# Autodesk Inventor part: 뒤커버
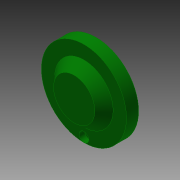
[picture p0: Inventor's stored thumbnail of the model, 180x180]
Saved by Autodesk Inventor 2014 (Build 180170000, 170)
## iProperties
Created: 2017-08
Part Number: 뒤커버
Material: 알루미늄 6061
Document SubType Name: Modeling
Designer: mduedu
Density: 1 g/cm^3
Appearance: 진녹색
Author: mduedu
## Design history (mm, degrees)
sketch "스케치1"
  geometry: C1 r 35 at (0, 0); 1 further point
  constraints: 1 centre point, 1 coincident
  dimensions: "d0" = 70 diameter of C1
extrude "돌출1" new body sketch "스케치1" distance "d1" = 10; taper "d2" = 0 deg
sketch "스케치2"
  geometry: C1 r 24 at (0, 0); 1 further point
  constraints: 1 centre point, 1 coincident
  dimensions: "d3" = 48 diameter of C1
node "작업 평면1"
sketch "스케치3"
  geometry: C1 r 17 at (0, 0); 1 further point
  constraints: 1 centre point, 1 coincident
  dimensions: "d5" = 34 diameter of C1
feature "로프트1" sketch "스케치3" dims "d6" = 0, "d7" = 90 deg, "d8" = 0, "d9" = 90 deg
sketch "스케치4"
  geometry: C1 r 24 at (0, 0) reference; 1 further point
extrude "돌출2" join sketch "스케치4" distance "d10" = 8; taper "d11" = 0 deg
hole "구멍1" diameter "d14" = 40; stored, may be unused: countersink angle "d18" = 90 deg, drill point angle "d20" = 0 deg; dims "d12" = 10, "d13" = 10, "d15" = 6, "d16" = 4, "d17" = 2, "d19" = 12
hole "구멍2" diameter "d23" = 34; stored, may be unused: countersink angle "d27" = 90 deg, drill point angle "d29" = 0 deg; dims "d24" = 6, "d25" = 4, "d26" = 2, "d28" = 6, "d62" = 10, "d63" = 10
chamfer "모따기1" distance "d39" = 1; stored, may be unused: second distance "d40" = 2, angle "d41" = 45 deg
fillet "모깎기1" dims "d42" = 0.3
fillet "모깎기2" dims "d43" = 3
fillet "모깎기3" dims "d56" = 3
sketch "스케치5" dims "d44" = 58
  geometry: 6 further points
  constraints: 2 vertical alignment, 1 coincident, 7 other
  dimensions: "d47" = 360 deg dimension on point (0, 0) point (0, 29) (derived)
sketch "스케치6" dims "d72" = 62
  geometry: C1 r 35 at (0, 0) reference; 2 further points
  constraints: 2 vertical alignment, 1 coincident, 2 other
hole "구멍4" sketch "스케치6" at (0, -31) diameter "d49" = 4.5; stored, may be unused: countersink angle "d53" = 90 deg, drill point angle "d55" = 0 deg; dims "d50" = 6, "d51" = 8, "d52" = 4.6, "d54" = 8
fillet "모깎기4" dims "d57" = 3
fillet "모깎기5" dims "d58" = 3
sketch "스케치7"
  geometry: L1 (-4, -31)-(4, -31); L2 (4, -31)-(4, -38); L3 (4, -38)-(-4, -38); L4 (-4, -38)-(-4, -31); 2 further points
  constraints: 8 end point, 2 parallel, 2 vertical, 1 horizontal, 1 midpoint, 1 perpendicular, 1 vertical alignment
  dimensions: "d65" = 7 distance of L1.end L2.end
extrude "돌출3" cut sketch "스케치7" stored distance "d67" = 10; taper "d68" = 0 deg
node "솔리드1"
pattern_circular "원형 패턴2" dims angle "d76" = 360 deg
pattern_circular "원형 패턴1" dims angle "d70" = 360 deg
other parameters: "d4" = 8
